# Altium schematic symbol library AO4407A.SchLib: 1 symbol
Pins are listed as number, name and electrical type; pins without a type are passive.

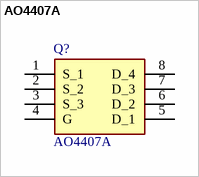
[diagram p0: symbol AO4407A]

## AO4407A
designator Q?
30V P-Channel MOSFET; Manufacturer_Name: Alpha & Omega Semiconductors; Geometry.Height: 1.75mm
footprint SOIC127P600X175-8N
pins: 1 S_1, 2 S_2, 3 S_3, 4 G, 5 D_1, 6 D_2, 7 D_3, 8 D_4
